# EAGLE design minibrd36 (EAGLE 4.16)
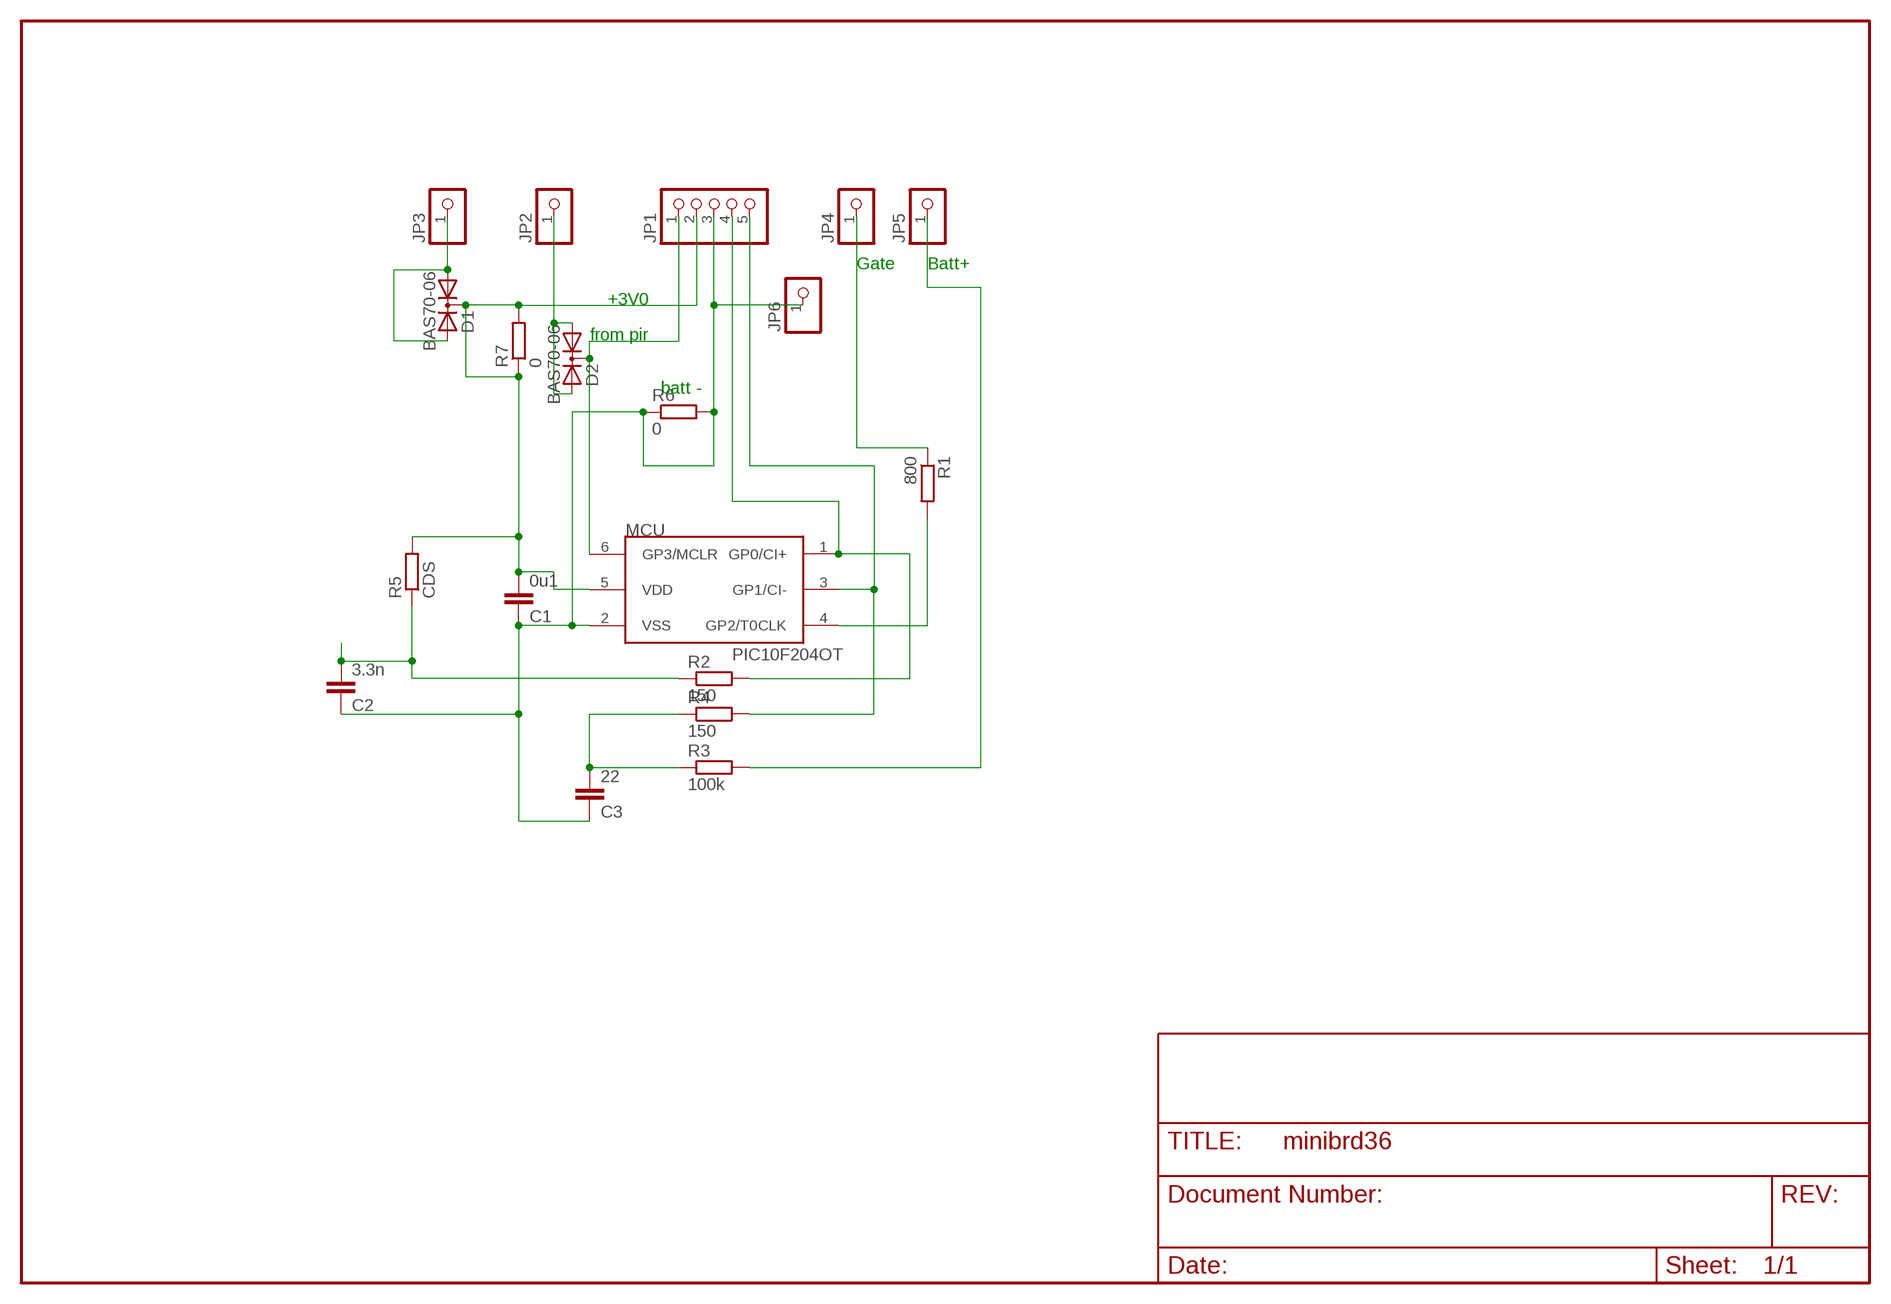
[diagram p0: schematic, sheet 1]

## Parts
C1  0u1  C-EUC1206  [C1206]
C2  3.3n  C-EUC1206  [C1206]
C3  22  C-EUC1206  [C1206]
D1  BAS70-06  [SOT23]
D2  BAS70-06  [SOT23]
JP1  PINHD-1X5  [1X05]
JP2  PINHD-1X1  [1X01]
JP3  PINHD-1X1  [1X01]
JP4  PINHD-1X1  [1X01]
JP5  PINHD-1X1  [1X01]
JP6  PINHD-1X1  [1X01]
MCU  PIC10F204OT  [SOT23-6]
R1  800  R-EU_R1206  [R1206]
R2  150  R-EU_R1206  [R1206]
R3  100k  R-EU_R1206  [R1206]
R4  150  R-EU_R1206  [R1206]
R5  CDS  R-EU_0613/5V  [P0613V]
R6  0  R-EU_R1206  [R1206]
R7  0  R-EU_R1206  [R1206]

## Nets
N$1: JP4.1 R1.1
N$2: C2.2 R2.1 R5.1
N$3: D1.1(A1) D1.2(A2) JP3.1
N$4: JP1.4 MCU.1(GP0/CI+) R2.2
N$5: MCU.4(GP2/T0CLK) R1.2
N$7: C3.2 R3.1 R4.1
N$8: JP1.5 MCU.3(GP1/CI-) R4.2
N$9: D2.1(A1) D2.2(A2) JP2.1
PIR: D2.3(C) JP1.1 MCU.6(GP3/MCLR)
V3: C1.2 D1.3(C) JP1.2 MCU.5(VDD) R5.2 R7.1 R7.2
V+: JP5.1 R3.2
V-: C1.1 C2.1 C3.1 JP1.3 JP6.1 MCU.2(VSS) R6.1 R6.2

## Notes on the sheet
- Gate | Batt+
- +3V0
- from pir
- batt -

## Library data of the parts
C1-C3 = rcl:C-EU: CAPACITOR, European symbol
D1 D2 = diode:BAS70-06: Silicon Schottky Diodes General-purpose diode for high-speed switching
JP1 = pinhead:PINHD-1X5: PIN HEADER
JP2-JP6 = pinhead:PINHD-1X1: PIN HEADER
MCU = microchip-3:PIC10F2*: uPC nW 0,25/0,5k Program Flash memory Comparator
R1-R7 = rcl:R-EU_: RESISTOR, European symbol

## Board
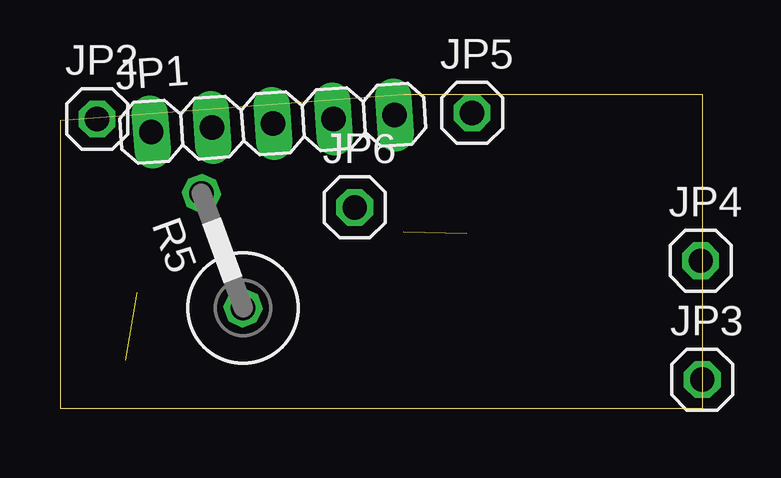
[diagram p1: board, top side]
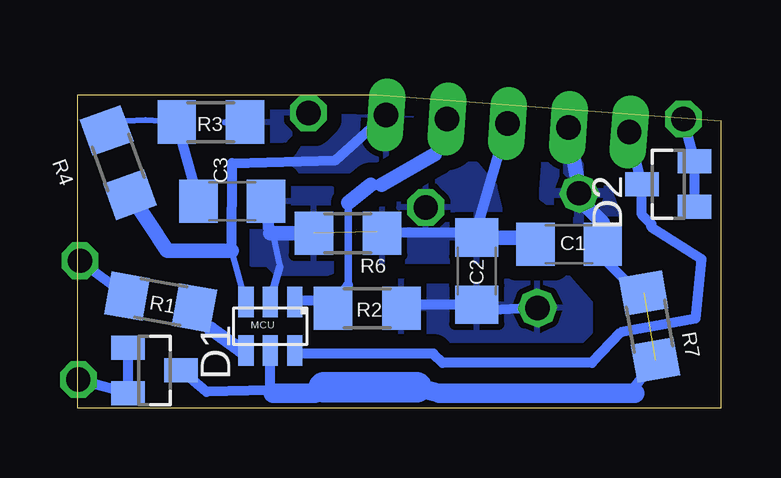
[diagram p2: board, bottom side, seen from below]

Size 26.78 x 13.08 mm. Coordinates in mm from the lower left corner, seen from the top.
Outline: 0,0 26.78,0 26.78,13.07 18,13.07 14.31,13.08 0,11.99 0,0
Copper layers (1*16): Top 0.035mm / dielectric 1.5mm / Bottom 0.035mm
Design rules "default": minimum track width 10mil, minimum drill 24mil, track to track 8mil, track to pad 8mil, pad to pad 8mil, via to via 8mil, smd to smd 8mil, copper to edge 1mil, drill to drill 8mil, minimum pad ring 10mil, minimum via ring 8mil, stop-mask expansion 4mil, vias tented up to drill 0mil, thermal gap 10mil

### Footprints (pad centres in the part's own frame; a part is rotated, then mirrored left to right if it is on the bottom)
C1206 = smd 1.6 x 1.8: 1 -1.4,0; 2 1.4,0
SOT23 = smd 1 x 1.4: 1 -0.95,-1.1; 2 0.95,-1.1; 3 0,1.1
1X05 = drill 1.016 long: 1 -5.08,0; 2 -2.54,0; 3 0,0; 4 2.54,0; 5 5.08,0
1X01 = drill 1.016 octagon: 1 0,0
SOT23-6 = smd 0.635 x 1.27: 1 -1.016,-1.016; 2 0,-1.016; 3 1.016,-1.016; 4 1.016,1.016; 5 0,1.016; 6 -1.016,1.016
R1206 = smd 1.6 x 1.803: 1 -1.422,0; 2 1.422,0
P0613V = drill 1.016 octagon: 1 -2.54,0; 2 2.54,0

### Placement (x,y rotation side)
C1  6.31,6.85 0 bottom
C2  10.16,5.72 270 bottom
C3  20.35,8.63 180 bottom
D1  23.58,1.58 270 bottom
D2  2.18,9.34 90 bottom
JP1  8.87,11.88 4 top
JP2  1.55,12.06 0 top
JP3  26.76,1.2 0 top
JP4  26.7,6.15 0 top
JP5  17.17,12.31 0 top
JP6  12.28,8.38 0 top
MCU  18.76,3.42 180 bottom
R1  23.32,4.43 350 bottom
R2  14.72,4.17 180 bottom
R3  21.23,11.93 0 bottom
R4  25.09,10.24 290 bottom
R5  6.76,6.58 110 top
R6  15.52,7.3 0 bottom
R7  2.96,3.41 280 bottom

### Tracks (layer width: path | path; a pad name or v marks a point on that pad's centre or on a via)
N$1
  Bottom 0.406: R1.1 JP4.1
N$2
  Bottom 0.406: R5.1 10.31,4.06 10.31,4.32 C2.2 13.23,4.32 13.23,4.17 R2.1
  pour Bottom (isolate 0.61, rank 2): 6.82,5.96 8.6,5.96 9.04,5.08 12.09,5.08 13.93,5.52 14.06,2.6 6.06,2.03 5.42,2.54 5.42,4.38
N$3
  Bottom 0.406: JP3.1 D1.2 D1.1
N$4
  Bottom 0.305: 15.52,5.14 15.52,8.57
  Bottom 0.406: 11.91,10.59 JP1.4 | 14.57,9.33 14.12,9.33 | 16,4.6 16.09,4.5 17.62,4.5 17.74,4.38 MCU.1 | 16,4.6 15.52,5.14 | 16,4.6 | R2.2 16.14,4.3 16,4.6
  Bottom 0.61: 14.12,9.33 11.91,10.59 | 15.52,8.57 14.57,9.33
N$5
  Bottom 0.254: MCU.4 19.99,2.42 | 21.23,3.31 R1.2
  Bottom 0.61: 19.99,2.42 21.23,3.31
N$7
  Bottom 0.254: R3.1 23.96,12.01 24.78,11.97 R4.1
  Bottom 0.406: C3.2 R3.1
N$8
  Bottom 0.254: MCU.3 20.36,6.57
  Bottom 0.406: JP1.5 16.03,10.35 20.35,10.22 20.36,6.57
  Bottom 0.61: 20.36,6.57 23.05,6.57 R4.2
  pour Bottom (isolate 0.61): 12.6,12.06 14.31,9.9 18.19,9.9 17.55,10.6 16.47,12.19
N$9
  Bottom 0.406: JP2.1 D2.2 D2.1
PIR
  Bottom 0.406: MCU.6 17.74,2.28 11.96,2.28 11.58,1.9 5.36,1.9 4.15,3.17 1.04,3.74 0.79,6.22 2.88,7.55 2.88,7.68 3.28,8.07 D2.3 JP1.1
V3  (1 unrouted)
  Bottom 0.254: R5.2 5.99,9.14 5.95,9.43
  Bottom 0.406: 18.76,0.76 MCU.5 | 18.63,0.63 18.76,0.76 | 3.58,0.63 3.71,0.76 R7.2 | 4.91,7.23 4.85,7.17 | 4.91,7.23 C1.2 4.91,6.27 3.64,5.01 3.1,4.91 R7.1 | 4.91,7.74 4.91,7.23 | D1.3 21.42,0.69 18.76,0.76
  Bottom 0.61: R5.2 6.31,9.14 4.91,7.74 | 5.95,9.43 JP1.2
  Bottom 0.813: 3.58,0.63 11.71,0.63 12.66,0.88 | 16.54,0.88 16.92,0.63 18.63,0.63
  Bottom 1.27: 12.66,0.88 16.54,0.88
  pour Bottom: 7.2,11.17 7.39,8.82 5.61,7.55 4.15,7.62 5.49,11.17
V+
  Bottom 0.254: 20.14,11.92 20.64,11.92 R3.2
  pour Bottom (isolate 0.61): 17.87,12.95 20.66,13.01 20.66,10.28 19.2,10.15 17.04,12.31
V-  (1 unrouted)
  Bottom 0.254: C3.1 18.37,5.9 | 18.69,4.76 MCU.2
  Bottom 0.305: 18.37,5.9 18.69,4.76
  Bottom 0.406: 18.76,7.3 18.82,7.36 C3.1 | C2.1 10.11,7.12 10.06,7.17 10.2,7.32 | 10.2,7.32 JP1.3 | C1.1 7.78,7.23 7.89,7.12 | 14.27,7.32 14.25,7.3 R6.2 | 10.2,7.32 14.27,7.32 | 14.27,7.32 14.31,7.36
  Bottom 0.61: R6.1 18.76,7.3 | C2.1 7.89,7.12
  pour Bottom (isolate 0.61): 10.19,10.15 11.58,10.15 12.09,10.09 13.49,8.69 13.74,8.69 14.57,7.87 14.57,6.15 9.17,6.15 9.17,8.25 9.42,9.27
  pour Bottom (isolate 0.406): 16.22,9.14 19.01,9.14 19.52,8.63 19.52,6.03 18.89,6.03 18.5,5.65 16.41,5.65 16.22,5.71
